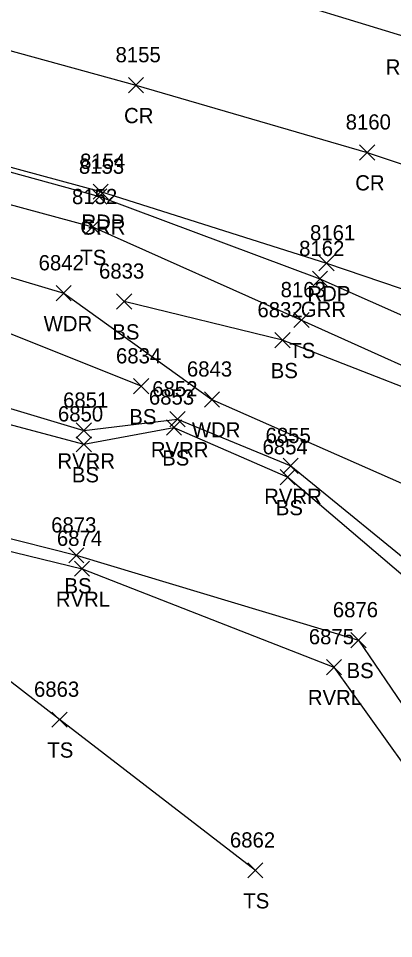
# Model space of a CAD drawing. Extents: x 1588028 to 1589597, y 137576 to 138176.
# Drawn here: x 1589076.8 to 1589126.2, y 137712.9 to 137833.8 of the extents above; entities that cross this region are included whole.
import ezdxf

# ---------------------------------------------------------------- set-up
doc = ezdxf.new("R2010")
doc.units = 0
for name, color, linetype in [('L_A', 7, 'Continuous'), ('L_I', 7, 'Continuous'), ('L_TIC', 7, 'Continuous'), ('LAWA', 7, 'Continuous'), ('LAWE', 7, 'Continuous'), ('LELB', 7, 'Continuous'), ('P_A', 7, 'Continuous'), ('P_I', 7, 'Continuous'), ('P_TIC', 7, 'Continuous'), ('PET', 7, 'Continuous'), ('PRC', 7, 'Continuous'), ('R_A', 7, 'Continuous'), ('R_I', 7, 'Continuous'), ('R_TIC', 7, 'Continuous'), ('RGR', 7, 'Continuous')]:
    doc.layers.add(name, color=color, linetype=linetype)

msp = doc.modelspace()

# ---------------------------------------------------------------- linework, layer by layer
at = {"layer": 'L_TIC'}
for points in [[(1589085.55, 137805.43), (1589087.55, 137807.43)], [(1589087.55, 137805.43), (1589085.55, 137807.43)], [(1589081.76, 137796.73), (1589083.76, 137798.73)], [(1589083.76, 137796.73), (1589081.76, 137798.73)], [(1589089.72, 137795.64), (1589091.72, 137797.64)], [(1589091.72, 137795.64), (1589089.72, 137797.64)], [(1589113.04, 137793.2), (1589115.04, 137795.2)], [(1589115.04, 137793.2), (1589113.04, 137795.2)], [(1589110.56, 137790.56), (1589112.56, 137792.56)], [(1589112.56, 137790.56), (1589110.56, 137792.56)], [(1589091.95, 137784.5), (1589093.95, 137786.5)], [(1589093.95, 137784.5), (1589091.95, 137786.5)], [(1589101.27, 137782.77), (1589103.27, 137784.77)], [(1589103.27, 137782.77), (1589101.27, 137784.77)], [(1589096.72, 137780.17), (1589098.72, 137782.17)], [(1589098.72, 137780.17), (1589096.72, 137782.17)], [(1589096.27, 137779.08), (1589098.27, 137781.08)], [(1589098.27, 137779.08), (1589096.27, 137781.08)], [(1589084.42, 137778.69), (1589086.42, 137780.69)], [(1589086.42, 137778.69), (1589084.42, 137780.69)], [(1589084.4, 137776.87), (1589086.4, 137778.87)], [(1589086.4, 137776.87), (1589084.4, 137778.87)], [(1589111.63, 137774.03), (1589113.63, 137776.03)], [(1589113.63, 137774.03), (1589111.63, 137776.03)], [(1589111.23, 137772.55), (1589113.23, 137774.55)], [(1589113.23, 137772.55), (1589111.23, 137774.55)], [(1589083.42, 137762.28), (1589085.42, 137764.28)], [(1589085.42, 137762.28), (1589083.42, 137764.28)], [(1589084.17, 137760.52), (1589086.17, 137762.52)], [(1589086.17, 137760.52), (1589084.17, 137762.52)], [(1589120.54, 137751.14), (1589122.54, 137753.14)], [(1589122.54, 137751.14), (1589120.54, 137753.14)], [(1589117.32, 137747.59), (1589119.32, 137749.59)], [(1589119.32, 137747.59), (1589117.32, 137749.59)], [(1589081.2, 137740.69), (1589083.2, 137742.69)], [(1589083.2, 137740.69), (1589081.2, 137742.69)], [(1589106.98, 137720.88), (1589108.98, 137722.88)], [(1589108.98, 137720.88), (1589106.98, 137722.88)]]:
    msp.add_lwpolyline(points, dxfattribs=at)
at = {"layer": 'LAWA'}
msp.add_lwpolyline([(1588990.27, 137820.39), (1589015.31, 137815.18), (1589044.24, 137809.21), (1589082.76, 137797.73), (1589102.27, 137783.77), (1589136.15, 137768.8), (1589160.7, 137757.03)], dxfattribs=at)
at = {"layer": 'LAWE'}
for points in [[(1588965.44, 137832.87), (1588973.43, 137818.62), (1588989.6, 137813.18), (1589022.84, 137804.12), (1589064.64, 137785.89), (1589085.42, 137779.69), (1589097.72, 137781.17), (1589112.63, 137775.03), (1589131.45, 137759.72), (1589147.93, 137745.25), (1589161.35, 137734.82)], [(1588998.37, 137781.01), (1589022.99, 137780.11), (1589053.11, 137769.29), (1589085.17, 137761.52), (1589118.32, 137748.59), (1589139.23, 137719.4), (1589162.49, 137704.02), (1589194.14, 137678.84), (1589218.55, 137662.87), (1589237.06, 137655.88), (1589274.24, 137640.2), (1589299.98, 137630.61), (1589325.3, 137627.35), (1589364.55, 137614.89), (1589400.15, 137603.63), (1589430.64, 137600.05), (1589464.28, 137596.09), (1589486.71, 137581.4)]]:
    msp.add_lwpolyline(points, dxfattribs=at)
at = {"layer": 'LELB'}
for points in [[(1588982.15, 137832.74), (1589014.45, 137822.9), (1589047.33, 137817.07), (1589086.55, 137806.43), (1589114.04, 137794.2), (1589138.04, 137783.39), (1589164.04, 137781.22)], [(1589092.95, 137785.5), (1589069.34, 137794.92), (1589055.55, 137800.72), (1589029.59, 137808.28), (1588996.95, 137815.45)], [(1588992.37, 137810.47), (1589023.33, 137801.66), (1589065.26, 137783.21), (1589085.4, 137777.87), (1589097.27, 137780.08), (1589112.23, 137773.55), (1589130.4, 137758.11), (1589147.06, 137743.95), (1589161.02, 137733.26), (1589186.97, 137714.57), (1589213.06, 137701.82), (1589227.47, 137691.94), (1589245.18, 137673.31), (1589268.48, 137660.8), (1589296.93, 137655.07), (1589325.66, 137650.73)], [(1589139.68, 137780.61), (1589111.56, 137791.56), (1589090.72, 137796.64)], [(1588992.54, 137792.39), (1589023.3, 137782.03), (1589052.1, 137771.44), (1589084.42, 137763.28), (1589121.54, 137752.14), (1589143.04, 137720.61), (1589163.05, 137704.95), (1589194.58, 137680.14), (1589220, 137665.12), (1589237.76, 137657.31), (1589273.63, 137642.37), (1589300.04, 137631.76), (1589324.52, 137628.67), (1589366.23, 137617.74), (1589400.05, 137606.05), (1589430.12, 137603.56), (1589464.26, 137598.64), (1589483.45, 137589.04)], [(1589107.98, 137721.88), (1589082.2, 137741.69), (1589059.2, 137759.51), (1589018.57, 137770.77), (1588998.03, 137776.52)]]:
    msp.add_lwpolyline(points, dxfattribs=at)
at = {"layer": 'P_TIC'}
for points in [[(1589091.27, 137824.07), (1589093.27, 137826.07)], [(1589093.27, 137824.07), (1589091.27, 137826.07)], [(1589121.68, 137815.23), (1589123.68, 137817.23)], [(1589123.68, 137815.23), (1589121.68, 137817.23)], [(1589086.62, 137810.07), (1589088.62, 137812.07)], [(1589088.62, 137810.07), (1589086.62, 137812.07)], [(1589116.34, 137800.67), (1589118.34, 137802.67)], [(1589118.34, 137800.67), (1589116.34, 137802.67)]]:
    msp.add_lwpolyline(points, dxfattribs=at)
at = {"layer": 'PET'}
for points in [[(1588976.42, 137837.98), (1588964.71, 137855.4), (1588953.74, 137871.46), (1588980.82, 137866.91), (1589021.21, 137859.55), (1589054.58, 137852.92), (1589087.36, 137843.77), (1589127.64, 137831.45), (1589150.05, 137824.37), (1589196.14, 137808.72), (1589243.87, 137790.96), (1589276.87, 137778.08), (1589322.25, 137759.62), (1589367.82, 137740.82), (1589401.87, 137726.11), (1589432.81, 137712.85), (1589459.76, 137701.46)], [(1588976.42, 137837.98), (1589015.38, 137829.77), (1589047.77, 137821.87), (1589087.62, 137811.07), (1589117.34, 137801.67), (1589165.82, 137785.25), (1589185.23, 137778.17), (1589232.28, 137760.8), (1589265.32, 137747.81), (1589310.31, 137729.83), (1589359.63, 137709.23), (1589389.55, 137696.8), (1589422.31, 137682.69), (1589446.91, 137672.54)]]:
    msp.add_lwpolyline(points, dxfattribs=at)
at = {"layer": 'PRC'}
msp.add_lwpolyline([(1588964.71, 137855.4), (1588980.14, 137852.51), (1589018.19, 137844.35), (1589051.57, 137836.27), (1589092.27, 137825.07), (1589122.68, 137816.23), (1589170.7, 137800.29), (1589190.72, 137793.38), (1589238.44, 137775.62), (1589271.31, 137762.4), (1589315.94, 137744.35), (1589366.22, 137723.58), (1589395.71, 137710.87), (1589428.18, 137697.42), (1589453.33, 137686.42)], dxfattribs=at)
at = {"layer": 'R_TIC'}
for points in [[(1589086.45, 137809.42), (1589088.45, 137811.42)], [(1589088.45, 137809.42), (1589086.45, 137811.42)], [(1589115.48, 137798.61), (1589117.48, 137800.61)], [(1589117.48, 137798.61), (1589115.48, 137800.61)]]:
    msp.add_lwpolyline(points, dxfattribs=at)
at = {"layer": 'RGR'}
msp.add_lwpolyline([(1588981.28, 137836.13), (1589015.23, 137828.95), (1589047.72, 137821.35), (1589087.45, 137810.42), (1589116.48, 137799.61), (1589136.35, 137790.83)], dxfattribs=at)

# ---------------------------------------------------------------- texts
at = {"layer": 'L_A'}
for s, p in [('TS', (1589084.95, 137801.43)), ('WDR', (1589080.12, 137792.73)), ('BS', (1589089.16, 137791.64)), ('TS', (1589112.45, 137789.2)), ('BS', (1589110, 137786.56)), ('BS', (1589091.39, 137780.5)), ('WDR', (1589099.63, 137778.77)), ('RVRR', (1589094.23, 137776.17)), ('RVRR', (1589081.93, 137774.69)), ('BS', (1589095.72, 137775.08)), ('BS', (1589083.84, 137772.87)), ('RVRR', (1589109.14, 137770.03)), ('BS', (1589110.67, 137768.55)), ('BS', (1589082.86, 137758.28)), ('RVRL', (1589081.73, 137756.52)), ('BS', (1589119.98, 137747.14)), ('RVRL', (1589114.89, 137743.59)), ('TS', (1589080.61, 137736.69)), ('TS', (1589106.39, 137716.88))]:
    msp.add_text(s, height=2, dxfattribs=at).set_placement(p)
at = {"layer": 'L_I'}
for s, p in [('8152', (1589083.85, 137809.43)), ('6842', (1589079.46, 137800.73)), ('6833', (1589087.41, 137799.64)), ('8163', (1589111.3, 137797.2)), ('6832', (1589108.25, 137794.56)), ('6834', (1589089.64, 137788.5)), ('6843', (1589098.97, 137786.77)), ('6852', (1589094.41, 137784.17)), ('6851', (1589082.68, 137782.69)), ('6853', (1589093.97, 137783.08)), ('6850', (1589082, 137780.87)), ('6855', (1589109.32, 137778.03)), ('6854', (1589108.92, 137776.55)), ('6873', (1589081.11, 137766.28)), ('6874', (1589081.86, 137764.52)), ('6876', (1589118.17, 137755.14)), ('6875', (1589115.01, 137751.59)), ('6863', (1589078.85, 137744.69)), ('6862', (1589104.63, 137724.88))]:
    msp.add_text(s, height=2, dxfattribs=at).set_placement(p)
at = {"layer": 'P_A'}
for s, p in [('RDP', (1589125.13, 137826.45)), ('CR', (1589090.7, 137820.07)), ('CR', (1589121.12, 137811.23)), ('RDP', (1589085.1, 137806.07)), ('RDP', (1589114.83, 137796.67))]:
    msp.add_text(s, height=2, dxfattribs=at).set_placement(p)
at = {"layer": 'P_I'}
for s, p in [('8155', (1589089.58, 137828.07)), ('8160', (1589119.86, 137819.23)), ('8154', (1589084.92, 137814.07)), ('8161', (1589115.17, 137804.67))]:
    msp.add_text(s, height=2, dxfattribs=at).set_placement(p)
at = {"layer": 'R_A'}
for p in [(1589084.94, 137805.42), (1589113.96, 137794.61)]:
    msp.add_text('GRR', height=2, dxfattribs=at).set_placement(p)
at = {"layer": 'R_I'}
for s, p in [('8153', (1589084.76, 137813.42)), ('8162', (1589113.74, 137802.61))]:
    msp.add_text(s, height=2, dxfattribs=at).set_placement(p)

doc.saveas('drawing.dxf')
